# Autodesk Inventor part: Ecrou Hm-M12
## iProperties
Created: 2011-10
Part Number: Ecrou Hm-M12
Document SubType Name: Modeling
Designer: A
Manufacturer: Standard
Standards Organization: Custom
Norme de conversion: STEP AP203
Nom du fichier: Ecrou Hm M12.STEP
Préprocesseur: SolidWorks 2006104
Postprocesseur: Build: 096e, Release: 9 RTM - Date: Thu 06/17/2004
Unités envoyées: MILLIMETERS
Incertitude: 1e-05
Author: A
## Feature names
1. Base1
